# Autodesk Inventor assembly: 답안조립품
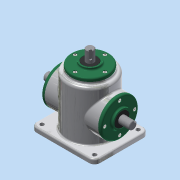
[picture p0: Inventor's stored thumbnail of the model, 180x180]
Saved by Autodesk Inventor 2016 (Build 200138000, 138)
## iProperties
Created: 2021-02
Part Number: 답안조립품
Material: 일반
Document SubType Name: Assembly
Designer: user
Author: user
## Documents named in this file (16)
- C:\Users\user\Desktop\710206V1002\답안조립품.iam
- C:\Users\user\Desktop\710206V1002\메인 베벨기어.ipt
- C:\Users\user\Desktop\710206V1002\메인 축.ipt
- 메인 축.ipt
- C:\Users\user\Desktop\710206V1002\베어링 6203.ipt
- C:\Users\user\Desktop\710206V1002\본체.ipt
- C:\Users\user\Desktop\710206V1002\볼트 M4.ipt
- 볼트 M4.ipt
- C:\Users\user\Desktop\710206V1002\서브 베벨기어.ipt
- C:\Users\user\Desktop\710206V1002\서브 축.ipt
- 서브 축.ipt
- C:\Users\user\Desktop\710206V1002\오일 실.ipt
- 오일 실.ipt
- C:\Users\user\Desktop\710206V1002\커버.ipt
- C:\Users\user\Desktop\710206V1002\키 4x4.ipt
- C:\Users\user\Desktop\710206V1002\키 5x5.ipt
